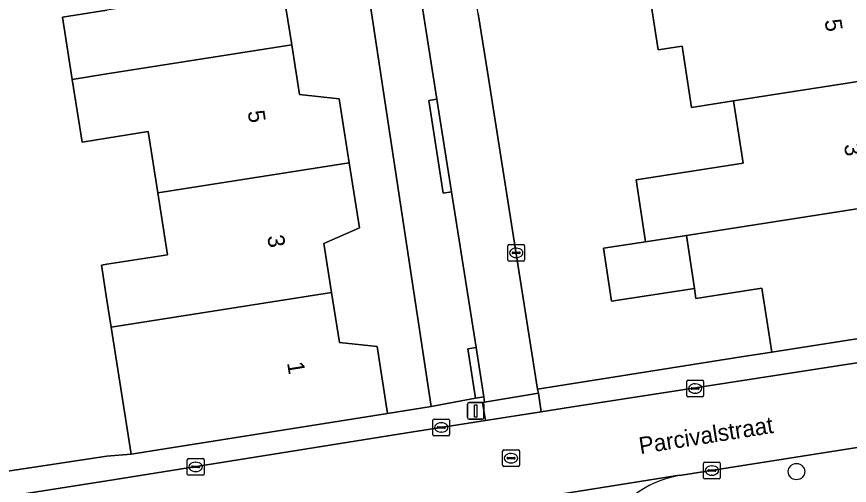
# Model space of a CAD drawing. Extents: x 160077 to 160948, y 386481 to 387498.
# Drawn here: x 160494.61 to 160544.36, y 387143.58 to 387171.58 of the extents above; entities that cross this region are included whole.
import ezdxf

# ---------------------------------------------------------------- set-up
doc = ezdxf.new("R2010")
doc.units = 0
for name, color, linetype in [('IMGEO_Boom', 7, 'Continuous'), ('IMGEO_Erf', 7, 'Continuous'), ('IMGEO_Kolk', 7, 'Continuous'), ('IMGEO_Lichtmast', 7, 'Continuous'), ('IMGEO_Muur', 7, 'Continuous'), ('IMGEO_Openbare_ruimte_label', 7, 'Continuous'), ('IMGEO_Pand', 7, 'Continuous'), ('IMGEO_Pand_nummerreeks', 7, 'Continuous'), ('IMGEO_Rijbaan_lokaal_open', 7, 'Continuous'), ('IMGEO_Rioolput', 7, 'Continuous'), ('IMGEO_Voetpad_open', 7, 'Continuous')]:
    doc.layers.add(name, color=color, linetype=linetype)

msp = doc.modelspace()

# ---------------------------------------------------------------- linework, layer by layer
at = {"layer": 'IMGEO_Boom'}
msp.add_circle((160541.197, 387144.403), 0.489, dxfattribs=at)
at = {"layer": 'IMGEO_Erf'}
for points in [[(160510.578, 387172.854), (160511.045, 387169.889), (160511.511, 387166.931), (160513.875, 387166.675), (160514.479, 387162.847), (160515.092, 387158.957), (160512.958, 387158.03), (160513.42, 387155.099), (160513.89, 387152.114), (160516.136, 387151.87), (160516.768, 387147.865), (160519.378, 387148.285), (160514.764, 387178.646)], [(160522.184, 387171.749), (160522.731, 387168.284), (160525.725, 387149.326), (160537.899, 387151.255), (160539.726, 387151.544), (160539.13, 387155.354), (160535.192, 387154.753), (160535.102, 387155.341), (160530.147, 387154.585), (160529.665, 387157.747), (160532.176, 387158.13), (160531.612, 387161.835), (160534.054, 387162.217), (160538.008, 387162.82), (160537.44, 387166.544), (160534.916, 387166.149), (160534.361, 387169.81), (160532.929, 387169.592), (160532.358, 387173.34)], [(160493.933, 387144.411), (160500, 387145.329), (160501.448, 387145.45), (160500.254, 387153.028), (160500, 387154.643), (160499.67, 387156.738), (160500, 387156.79), (160503.621, 387157.361), (160503.04, 387161.048), (160502.463, 387164.71), (160500, 387164.322), (160498.511, 387164.087), (160497.922, 387167.825), (160497.336, 387171.545), (160500, 387171.966)]]:
    msp.add_lwpolyline(points, dxfattribs=at)
at = {"layer": 'IMGEO_Kolk'}
for p, q in [((160524.027, 387157.97), (160524.879, 387157.97)), ((160523.952, 387157.044), (160523.952, 387157.896)), ((160524.211, 387157.464), (160524.211, 387157.476)), ((160524.649, 387157.427), (160524.251, 387157.427)), ((160524.254, 387157.513), (160524.652, 387157.513)), ((160524.44, 387157.75), (160524.465, 387157.75)), ((160524.695, 387157.476), (160524.695, 387157.464)), ((160524.953, 387157.896), (160524.953, 387157.044)), ((160524.879, 387156.97), (160524.027, 387156.97)), ((160524.463, 387157.19), (160524.438, 387157.19)), ((160534.643, 387148.941), (160534.643, 387149.793)), ((160534.718, 387149.867), (160535.57, 387149.867)), ((160535.131, 387149.647), (160535.156, 387149.647)), ((160535.644, 387149.793), (160535.644, 387148.941)), ((160534.902, 387149.361), (160534.902, 387149.373)), ((160535.34, 387149.324), (160534.942, 387149.324)), ((160534.945, 387149.41), (160535.343, 387149.41)), ((160535.154, 387149.087), (160535.129, 387149.087)), ((160535.386, 387149.373), (160535.386, 387149.361)), ((160535.57, 387148.867), (160534.718, 387148.867)), ((160519.472, 387146.616), (160519.472, 387147.468)), ((160519.547, 387147.542), (160520.399, 387147.542)), ((160520.473, 387147.468), (160520.473, 387146.616)), ((160519.731, 387147.036), (160519.731, 387147.048)), ((160520.169, 387146.999), (160519.771, 387146.999)), ((160519.774, 387147.085), (160520.172, 387147.085)), ((160519.96, 387147.322), (160519.985, 387147.322)), ((160520.215, 387147.048), (160520.215, 387147.036)), ((160520.399, 387146.542), (160519.547, 387146.542)), ((160519.983, 387146.762), (160519.958, 387146.762)), ((160504.802, 387144.26), (160504.802, 387145.112)), ((160504.877, 387145.186), (160505.729, 387145.186)), ((160505.803, 387145.112), (160505.803, 387144.26)), ((160505.061, 387144.68), (160505.061, 387144.692)), ((160505.499, 387144.643), (160505.101, 387144.643)), ((160505.104, 387144.729), (160505.502, 387144.729)), ((160505.29, 387144.966), (160505.315, 387144.966)), ((160505.545, 387144.692), (160505.545, 387144.68)), ((160535.642, 387144.042), (160535.642, 387144.894)), ((160535.717, 387144.968), (160536.569, 387144.968)), ((160535.944, 387144.511), (160536.342, 387144.511)), ((160536.13, 387144.748), (160536.155, 387144.748)), ((160536.643, 387144.894), (160536.643, 387144.042)), ((160505.729, 387144.186), (160504.877, 387144.186)), ((160505.313, 387144.406), (160505.288, 387144.406)), ((160535.901, 387144.462), (160535.901, 387144.474)), ((160536.339, 387144.425), (160535.941, 387144.425)), ((160536.153, 387144.188), (160536.128, 387144.188)), ((160536.385, 387144.474), (160536.385, 387144.462)), ((160536.569, 387143.968), (160535.717, 387143.968))]:
    msp.add_line(p, q, dxfattribs=at)
for points in [[(160524.027, 387157.97), (160524.879, 387157.97)], [(160523.952, 387157.044), (160523.952, 387157.896)], [(160524.953, 387157.896), (160524.953, 387157.044)], [(160524.879, 387156.97), (160524.027, 387156.97)], [(160534.643, 387148.941), (160534.643, 387149.793)], [(160534.718, 387149.867), (160535.57, 387149.867)], [(160535.644, 387149.793), (160535.644, 387148.941)], [(160535.57, 387148.867), (160534.718, 387148.867)], [(160519.472, 387146.616), (160519.472, 387147.468)], [(160519.547, 387147.542), (160520.399, 387147.542)], [(160520.473, 387147.468), (160520.473, 387146.616)], [(160520.399, 387146.542), (160519.547, 387146.542)], [(160504.802, 387144.26), (160504.802, 387145.112)], [(160504.877, 387145.186), (160505.729, 387145.186)], [(160505.803, 387145.112), (160505.803, 387144.26)], [(160535.642, 387144.042), (160535.642, 387144.894)], [(160535.717, 387144.968), (160536.569, 387144.968)], [(160536.643, 387144.894), (160536.643, 387144.042)], [(160505.729, 387144.186), (160504.877, 387144.186)], [(160536.569, 387143.968), (160535.717, 387143.968)]]:
    msp.add_lwpolyline(points, dxfattribs=at)
for centre, radius, start, end in [((160524.029, 387157.894), 0.0765, 91.552, 178.448), ((160524.029, 387157.894), 0.0765, 91.552, 178.448), ((160524.877, 387157.894), 0.0765, 1.552, 88.448), ((160524.877, 387157.894), 0.0765, 1.552, 88.448), ((160524.251, 387157.473), 0.0403, 85.8775, 175.7526), ((160524.248, 387157.463), 0.0366, 178.938, 274.7102), ((160524.652, 387157.47), 0.043, 264.8664, 352.4533), ((160524.656, 387157.475), 0.0386, 1.7309, 96.639), ((160524.029, 387157.046), 0.0765, 181.552, 268.448), ((160524.029, 387157.046), 0.0765, 181.552, 268.448), ((160524.877, 387157.046), 0.0765, 271.552, 358.448), ((160524.877, 387157.046), 0.0765, 271.552, 358.448), ((160534.72, 387149.791), 0.0765, 91.552, 178.448), ((160534.72, 387149.791), 0.0765, 91.552, 178.448), ((160535.568, 387149.791), 0.0765, 1.552, 88.448), ((160535.568, 387149.791), 0.0765, 1.552, 88.448), ((160534.942, 387149.37), 0.0403, 85.8775, 175.7526), ((160534.939, 387149.36), 0.0366, 178.938, 274.7102), ((160535.343, 387149.367), 0.043, 264.8664, 352.4533), ((160535.347, 387149.372), 0.0386, 1.7309, 96.639), ((160534.72, 387148.943), 0.0765, 181.552, 268.448), ((160534.72, 387148.943), 0.0765, 181.552, 268.448), ((160535.568, 387148.943), 0.0765, 271.552, 358.448), ((160535.568, 387148.943), 0.0765, 271.552, 358.448), ((160519.549, 387147.466), 0.0765, 91.552, 178.448), ((160519.549, 387147.466), 0.0765, 91.552, 178.448), ((160520.397, 387147.466), 0.0765, 1.552, 88.448), ((160520.397, 387147.466), 0.0765, 1.552, 88.448), ((160519.771, 387147.045), 0.0403, 85.8775, 175.7526), ((160519.768, 387147.035), 0.0366, 178.938, 274.7102), ((160520.172, 387147.042), 0.043, 264.8664, 352.4533), ((160520.176, 387147.047), 0.0386, 1.7309, 96.639), ((160519.549, 387146.618), 0.0765, 181.552, 268.448), ((160519.549, 387146.618), 0.0765, 181.552, 268.448), ((160520.397, 387146.618), 0.0765, 271.552, 358.448), ((160520.397, 387146.618), 0.0765, 271.552, 358.448), ((160504.879, 387145.11), 0.0765, 91.552, 178.448), ((160504.879, 387145.11), 0.0765, 91.552, 178.448), ((160505.727, 387145.11), 0.0765, 1.552, 88.448), ((160505.727, 387145.11), 0.0765, 1.552, 88.448), ((160505.101, 387144.689), 0.0403, 85.8775, 175.7526), ((160505.098, 387144.679), 0.0366, 178.938, 274.7102), ((160505.502, 387144.686), 0.043, 264.8664, 352.4533), ((160505.506, 387144.691), 0.0386, 1.7309, 96.639), ((160535.719, 387144.892), 0.0765, 91.552, 178.448), ((160535.719, 387144.892), 0.0765, 91.552, 178.448), ((160535.941, 387144.471), 0.0403, 85.8775, 175.7526), ((160536.346, 387144.473), 0.0386, 1.7309, 96.639), ((160536.567, 387144.892), 0.0765, 1.552, 88.448), ((160536.567, 387144.892), 0.0765, 1.552, 88.448), ((160504.879, 387144.262), 0.0765, 181.552, 268.448), ((160504.879, 387144.262), 0.0765, 181.552, 268.448), ((160505.727, 387144.262), 0.0765, 271.552, 358.448), ((160505.727, 387144.262), 0.0765, 271.552, 358.448), ((160535.719, 387144.044), 0.0765, 181.552, 268.448), ((160535.719, 387144.044), 0.0765, 181.552, 268.448), ((160535.938, 387144.461), 0.0366, 178.938, 274.7102), ((160536.342, 387144.468), 0.043, 264.8664, 352.4533), ((160536.567, 387144.044), 0.0765, 271.552, 358.448), ((160536.567, 387144.044), 0.0765, 271.552, 358.448)]:
    msp.add_arc(centre, radius, start, end, dxfattribs=at)
for centre, major_axis, ratio, start_param, end_param in [((160524.439, 387157.47), (-0.387, 0.002), 0.722429, 4.712389, 7.853982), ((160524.464, 387157.47), (-0.39, 0.002), 0.717154, 1.570796, 4.712389), ((160535.13, 387149.367), (-0.387, 0.002), 0.722429, 4.712389, 7.853982), ((160535.155, 387149.367), (-0.39, 0.002), 0.717154, 1.570796, 4.712389), ((160519.959, 387147.042), (-0.387, 0.002), 0.722429, 4.712389, 7.853982), ((160519.984, 387147.042), (-0.39, 0.002), 0.717154, 1.570796, 4.712389), ((160505.289, 387144.686), (-0.387, 0.002), 0.722429, 4.712389, 7.853982), ((160505.314, 387144.686), (-0.39, 0.002), 0.717154, 1.570796, 4.712389), ((160536.129, 387144.468), (-0.387, 0.002), 0.722429, 4.712389, 7.853982), ((160536.154, 387144.468), (-0.39, 0.002), 0.717154, 1.570796, 4.712389)]:
    msp.add_ellipse(centre, major_axis=major_axis, ratio=ratio, start_param=start_param, end_param=end_param, dxfattribs=at)
at = {"layer": 'IMGEO_Lichtmast'}
for p, q in [((160521.633, 387148.527), (160522.423, 387148.527)), ((160522.423, 387148.527), (160521.633, 387148.527)), ((160521.533, 387147.627), (160521.533, 387148.427)), ((160521.533, 387148.427), (160521.533, 387147.627)), ((160522.523, 387148.427), (160522.523, 387147.627)), ((160522.523, 387147.627), (160522.523, 387148.427)), ((160522.423, 387147.527), (160521.633, 387147.527)), ((160521.633, 387147.527), (160522.423, 387147.527))]:
    msp.add_line(p, q, dxfattribs=at)
msp.add_lwpolyline([(160521.953, 387148.402), (160522.103, 387148.402), (160522.103, 387147.652), (160521.953, 387147.652), (160521.953, 387148.402)], dxfattribs=at)
for centre, start, end in [((160521.633, 387148.427), 90, 180), ((160521.633, 387148.427), 90, 180), ((160522.423, 387148.427), 0, 90), ((160522.423, 387148.427), 360, 90), ((160521.633, 387147.627), 180, 270), ((160521.633, 387147.627), 180, 270), ((160522.423, 387147.627), 270, 0), ((160522.423, 387147.627), 270, 0)]:
    msp.add_arc(centre, 0.1, start, end, dxfattribs=at)
at = {"layer": 'IMGEO_Muur'}
msp.add_lwpolyline([(160539.726, 387151.544), (160537.899, 387151.255)], dxfattribs=at)
at = {"layer": 'IMGEO_Pand'}
for points in [[(160511.045, 387169.889), (160510.578, 387172.854), (160512.731, 387173.778), (160512.122, 387177.642), (160500.707, 387175.846), (160501.287, 387172.168), (160500, 387171.966), (160497.336, 387171.545), (160497.922, 387167.825), (160500, 387168.152)], [(160548.402, 387172.097), (160545.968, 387172.349), (160545.492, 387175.394), (160532.358, 387173.34), (160532.929, 387169.592), (160534.361, 387169.81), (160534.916, 387166.149), (160537.44, 387166.544), (160548.988, 387168.35)], [(160500, 387168.152), (160497.922, 387167.825), (160498.511, 387164.087), (160500, 387164.322), (160502.463, 387164.71), (160503.04, 387161.048), (160514.479, 387162.847), (160513.875, 387166.675), (160511.511, 387166.931), (160511.045, 387169.889)], [(160537.44, 387166.544), (160538.008, 387162.82), (160534.054, 387162.217), (160531.612, 387161.835), (160532.176, 387158.13), (160534.619, 387158.512), (160547.87, 387160.585), (160547.403, 387163.572), (160549.6, 387164.439), (160548.988, 387168.35)], [(160513.42, 387155.099), (160512.958, 387158.03), (160515.092, 387158.957), (160514.479, 387162.847), (160503.04, 387161.048), (160503.621, 387157.361), (160500, 387156.79), (160499.67, 387156.738), (160500, 387154.643), (160500.254, 387153.028)], [(160550.632, 387157.376), (160548.335, 387157.608), (160547.87, 387160.585), (160534.619, 387158.512), (160535.102, 387155.341), (160535.192, 387154.753), (160539.13, 387155.354), (160539.726, 387151.544), (160551.261, 387153.348)], [(160534.619, 387158.512), (160532.176, 387158.13), (160529.665, 387157.747), (160530.147, 387154.585), (160535.102, 387155.341)], [(160516.768, 387147.865), (160516.136, 387151.87), (160513.89, 387152.114), (160513.42, 387155.099), (160500.254, 387153.028), (160501.448, 387145.45)]]:
    msp.add_lwpolyline(points, close=True, dxfattribs=at)
at = {"layer": 'IMGEO_Rijbaan_lokaal_open'}
msp.add_lwpolyline([(160525.778, 387149.084), (160525.725, 387149.326), (160522.731, 387168.284), (160522.184, 387171.749), (160521.734, 387174.596), (160517.066, 387204.154), (160513.988, 387203.613), (160515.125, 387196.205), (160515.927, 387190.987), (160517.401, 387181.386), (160517.762, 387179.037), (160518.256, 387175.902), (160519.716, 387166.643), (160520.588, 387161.109), (160522.053, 387151.816), (160522.517, 387148.875), (160522.567, 387148.56)], close=True, dxfattribs=at)
for points in [[(160551.502, 387151.942), (160527.693, 387148.256), (160525.948, 387147.982), (160522.624, 387147.455), (160518.297, 387146.776), (160500, 387143.854), (160493.782, 387142.868), (160463.21, 387138.021)], [(160461.484, 387132.784), (160462.906, 387132.966), (160489.417, 387137.116), (160500, 387138.779), (160517.735, 387141.567), (160517.975, 387141.6), (160534.205, 387144.195), (160534.212, 387144.165), (160560.487, 387148.307)], [(160534.212, 387144.165), (160534.205, 387144.195), (160517.975, 387141.6)]]:
    msp.add_lwpolyline(points, dxfattribs=at)
msp.add_arc((160535.149, 387138.221), 6.017, 98.9625, 157.23, dxfattribs=at)
at = {"layer": 'IMGEO_Rioolput'}
for p, q in [((160523.641, 387144.78), (160523.641, 387145.632)), ((160523.716, 387145.706), (160524.568, 387145.706)), ((160524.129, 387145.486), (160524.154, 387145.486)), ((160524.642, 387145.632), (160524.642, 387144.78)), ((160523.9, 387145.2), (160523.9, 387145.212)), ((160524.338, 387145.163), (160523.94, 387145.163)), ((160523.943, 387145.249), (160524.341, 387145.249)), ((160524.384, 387145.212), (160524.384, 387145.2)), ((160524.568, 387144.706), (160523.716, 387144.706)), ((160524.152, 387144.926), (160524.127, 387144.926))]:
    msp.add_line(p, q, dxfattribs=at)
for points in [[(160523.641, 387144.78), (160523.641, 387145.632)], [(160523.716, 387145.706), (160524.568, 387145.706)], [(160524.642, 387145.632), (160524.642, 387144.78)], [(160524.568, 387144.706), (160523.716, 387144.706)]]:
    msp.add_lwpolyline(points, dxfattribs=at)
for centre, radius, start, end in [((160523.718, 387145.63), 0.0765, 91.552, 178.448), ((160523.718, 387145.63), 0.0765, 91.552, 178.448), ((160524.566, 387145.63), 0.0765, 1.552, 88.448), ((160524.566, 387145.63), 0.0765, 1.552, 88.448), ((160523.94, 387145.209), 0.0403, 85.8775, 175.7526), ((160523.937, 387145.199), 0.0366, 178.938, 274.7102), ((160524.341, 387145.206), 0.043, 264.8664, 352.4533), ((160524.345, 387145.211), 0.0386, 1.7309, 96.639), ((160523.718, 387144.782), 0.0765, 181.552, 268.448), ((160523.718, 387144.782), 0.0765, 181.552, 268.448), ((160524.566, 387144.782), 0.0765, 271.552, 358.448), ((160524.566, 387144.782), 0.0765, 271.552, 358.448)]:
    msp.add_arc(centre, radius, start, end, dxfattribs=at)
for centre, major_axis, ratio, start_param, end_param in [((160524.128, 387145.206), (-0.387, 0.002), 0.722429, 4.712389, 7.853982), ((160524.153, 387145.206), (-0.39, 0.002), 0.717154, 1.570796, 4.712389)]:
    msp.add_ellipse(centre, major_axis=major_axis, ratio=ratio, start_param=start_param, end_param=end_param, dxfattribs=at)
at = {"layer": 'IMGEO_Voetpad_open'}
for points in [[(160510.656, 387204.038), (160514.764, 387178.646), (160519.378, 387148.285), (160522.023, 387148.799), (160521.559, 387151.74), (160522.053, 387151.816), (160520.588, 387161.109), (160520.095, 387161.032), (160519.223, 387166.566), (160519.716, 387166.643), (160518.256, 387175.902), (160517.762, 387175.827), (160516.907, 387181.311), (160517.401, 387181.386), (160515.927, 387190.987), (160515.433, 387190.912), (160514.631, 387196.13)], [(160622.849, 387158.043), (160621.92, 387157.879), (160611.294, 387156.291), (160601.186, 387154.687), (160601.189, 387154.665), (160595.546, 387153.889), (160566.846, 387149.32), (160563.387, 387148.767), (160562.894, 387148.69), (160560.487, 387148.307), (160534.212, 387144.165)], [(160551.261, 387153.348), (160539.726, 387151.544), (160537.899, 387151.255), (160525.725, 387149.326), (160525.778, 387149.084), (160525.948, 387147.982), (160527.693, 387148.256), (160551.502, 387151.942)], [(160493.782, 387142.868), (160500, 387143.854), (160518.297, 387146.776), (160522.624, 387147.455), (160522.443, 387148.54), (160522.567, 387148.56), (160522.517, 387148.875), (160522.023, 387148.799), (160519.378, 387148.285), (160516.768, 387147.865), (160501.448, 387145.45), (160500, 387145.329), (160493.933, 387144.411), (160493.093, 387149.407), (160492.562, 387152.579), (160492.554, 387152.587)]]:
    msp.add_lwpolyline(points, dxfattribs=at)
for points in [[(160519.716, 387166.643), (160519.223, 387166.566), (160520.095, 387161.032), (160520.588, 387161.109)], [(160522.517, 387148.875), (160522.053, 387151.816), (160521.559, 387151.74), (160522.023, 387148.799)], [(160525.948, 387147.982), (160525.778, 387149.084), (160522.567, 387148.56), (160522.443, 387148.54), (160522.624, 387147.455)]]:
    msp.add_lwpolyline(points, close=True, dxfattribs=at)
msp.add_arc((160535.149, 387138.221), 6.017, 98.9625, 157.23, dxfattribs=at)

# ---------------------------------------------------------------- texts
at = {"layer": 'IMGEO_Openbare_ruimte_label'}
msp.add_text('Parcivalstraat', height=1, rotation=9.0292, dxfattribs=at).set_placement((160531.866, 387145.449))
at = {"layer": 'IMGEO_Pand_nummerreeks'}
for s, rotation, p in [('5', 278.8692, (160542.872, 387171.359)), ('5', 278.9353, (160508.401, 387165.912)), ('3', 278.8684, (160544.031, 387163.924)), ('3', 278.9353, (160509.572, 387158.462)), ('1', 278.9353, (160510.761, 387150.901))]:
    msp.add_text(s, height=1, rotation=rotation, dxfattribs=at).set_placement(p)

doc.saveas('drawing.dxf')
